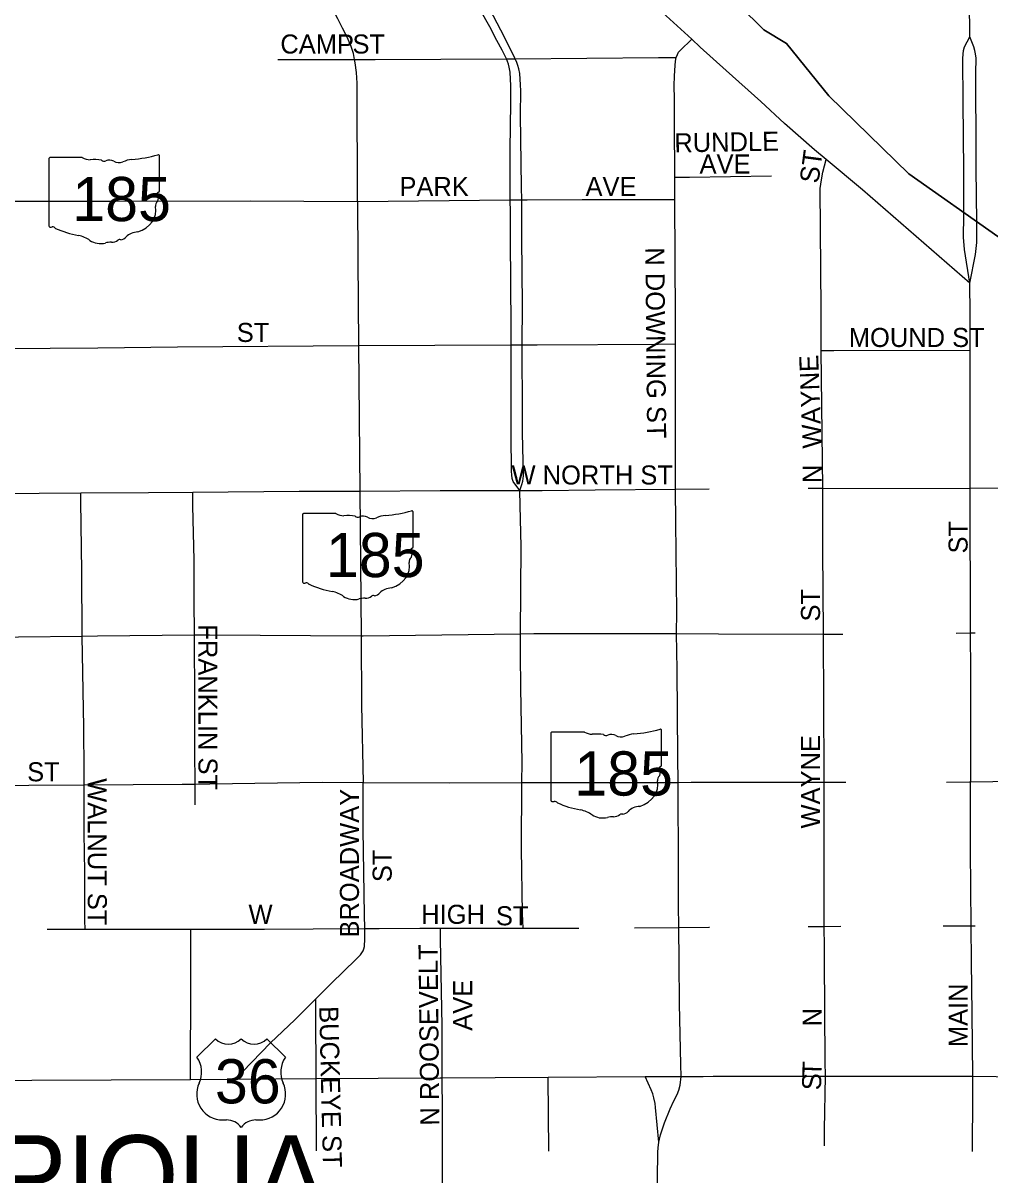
# Model space of a CAD drawing. Extents: x -87 to 2145, y -2128 to 440.
# Drawn here: x 533.8 to 609.9, y -568.8 to -478.1 of the extents above; entities that cross this region are included whole.
import ezdxf

# ---------------------------------------------------------------- set-up
doc = ezdxf.new("R2010")
doc.units = 0
for name, color, linetype in [('Default', 7, 'Continuous'), ('GM_X_City_Street', 7, 'Continuous'), ('GM_X_City_Street_Text', 7, 'Continuous'), ('GM_X_County_Road', 7, 'Continuous'), ('GM_X_State_Route', 7, 'Continuous'), ('GM_X_State_Shield', 7, 'Continuous'), ('GM_X_Township', 7, 'Continuous'), ('GM_X_US_Route', 7, 'Continuous'), ('GM_X_US_Shield', 7, 'Continuous')]:
    doc.layers.add(name, color=color, linetype=linetype)

msp = doc.modelspace()

# ---------------------------------------------------------------- linework, layer by layer
at = {"layer": 'Default'}
msp.add_circle((574.695, -533.387), 114.662, dxfattribs=at)
at = {"layer": 'GM_X_City_Street'}
for p, q in [((585.143, -514.819), (587.781, -514.8)), ((595.574, -514.742), (596.744, -514.734)), ((607.228, -526.149), (608.37, -526.135)), ((608.37, -526.135), (608.731, -526.137)), ((547.332, -539.66), (547.318, -538.032)), ((538.657, -549.463), (546.988, -549.456)), ((581.922, -549.35), (585.395, -549.325)), ((596.846, -549.232), (598.142, -549.227)), ((606.217, -549.189), (608.73, -549.192)), ((608.448, -552.036), (608.42, -549.191))]:
    msp.add_line(p, q, dxfattribs=at)
for points in [[(572.52, -480.945), (572.501, -480.904), (572.365, -480.612), (571.396, -478.679), (570.535, -477.026), (569.383, -474.98), (568.134, -472.73), (566.342, -469.116), (565.395, -467.299), (565.048, -466.741), (564.708, -466.247), (564.306, -465.722), (563.977, -465.454)], [(571.846, -480.948), (571.733, -480.732), (571.593, -480.466), (571.499, -480.266), (571.086, -479.505), (570.53, -478.438), (568.243, -474.397), (566.773, -471.457), (565.435, -468.813), (564.82, -467.586), (564.291, -466.513), (564.106, -466.077), (564.029, -465.816), (563.977, -465.454)], [(559.875, -480.99), (559.79, -480.517), (559.595, -479.981), (559.29, -479.248), (558.935, -478.528), (558.569, -477.808), (558.115, -476.944), (557.634, -476.01), (557.033, -474.846), (556.128, -473.097), (555.365, -471.622), (554.455, -469.86), (554.33, -469.617)], [(585.192, -480.833), (585.192, -480.83), (585.29, -480.592), (585.387, -480.43), (585.517, -480.3), (586.418, -479.398)], [(553.829, -480.995), (559.875, -480.99)], [(559.875, -480.99), (561.493, -480.988), (571.846, -480.948)], [(560.113, -492.173), (560.071, -482.874), (560.022, -482.019), (559.924, -481.262), (559.875, -480.99)], [(571.846, -480.948), (572.225, -480.946), (572.52, -480.945)], [(572.134, -492.049), (572.131, -491.45), (572.135, -488.089), (572.176, -484.445), (572.18, -483.067), (572.124, -481.99), (572.054, -481.606), (571.985, -481.377), (571.846, -480.948)], [(572.52, -480.945), (583.792, -480.845), (585.192, -480.833)], [(573.029, -492.04), (573.023, -491.049), (572.942, -485.344), (572.951, -483.464), (572.937, -483.001), (572.882, -482.113), (572.817, -481.72), (572.737, -481.48), (572.659, -481.245), (572.52, -480.945)], [(585.084, -490.272), (585.054, -485.976), (585.052, -484.102), (585.041, -483.072), (585.062, -482.292), (585.106, -481.48), (585.138, -481.123), (585.192, -480.833)], [(596.595, -503.899), (596.597, -500.678), (596.531, -491.161), (596.638, -490.48), (596.743, -489.863), (596.994, -488.876)], [(585.084, -490.272), (586.228, -490.254), (592.706, -490.151)], [(585.096, -492.015), (585.095, -491.921), (585.084, -490.272)], [(560.113, -492.173), (572.134, -492.049)], [(572.134, -492.049), (573.029, -492.04)], [(572.205, -503.459), (572.207, -502.046), (572.139, -495.171), (572.14, -493.004), (572.134, -492.049)], [(573.029, -492.04), (573.464, -492.035), (577.79, -492.018), (583.847, -492.016), (585.096, -492.015)], [(573.077, -503.455), (573.085, -500.342), (573.034, -495.052), (573.037, -493.438), (573.029, -492.04)], [(585.135, -503.392), (585.13, -501.319), (585.096, -492.015)], [(608.319, -498.615), (607.882, -495.963), (607.817, -494.979), (607.822, -494.687), (607.841, -493.576), (607.843, -493.46)], [(608.319, -498.615), (608.748, -496.357), (608.849, -495.412), (608.849, -495.346), (608.848, -494.198), (608.848, -494.19)], [(527.804, -503.767), (528.379, -503.762), (539.67, -503.692), (545.941, -503.608), (560.179, -503.512)], [(560.179, -503.512), (572.205, -503.459)], [(572.873, -514.922), (572.354, -514.222), (572.28, -513.971), (572.243, -513.704), (572.239, -513.439), (572.201, -510.58), (572.211, -508.125), (572.205, -503.736), (572.205, -503.459)], [(572.205, -503.459), (573.077, -503.455)], [(572.873, -514.922), (573.048, -514.443), (573.122, -514.178), (573.167, -513.778), (573.097, -510.397), (573.095, -507.916), (573.074, -504.447), (573.077, -503.455)], [(573.077, -503.455), (574.245, -503.45), (583.784, -503.399), (585.135, -503.392)], [(585.143, -514.819), (585.137, -513.766), (585.147, -507.878), (585.135, -503.392)], [(596.595, -503.899), (597.591, -503.897), (608.327, -503.87)], [(596.744, -514.734), (596.595, -503.899)], [(547.133, -515.046), (555.523, -514.986), (556.699, -514.986), (560.297, -514.967)], [(560.297, -514.967), (566.617, -514.933), (571.81, -514.925), (572.873, -514.922)], [(572.873, -514.922), (574.645, -514.917), (578.809, -514.866), (585.143, -514.819)], [(572.947, -526.204), (572.99, -519.339), (572.904, -516.098), (572.873, -514.922)], [(585.221, -526.186), (585.235, -524.499), (585.16, -517.405), (585.143, -514.819)], [(596.744, -514.734), (608.348, -514.775)], [(596.778, -526.238), (596.778, -526.119), (596.747, -519.584), (596.744, -514.734)], [(608.37, -526.135), (608.348, -514.775)], [(527.936, -515.185), (528.491, -515.184), (538.327, -515.11)], [(538.327, -515.11), (543.649, -515.07), (547.133, -515.046)], [(538.419, -526.38), (538.394, -521.276), (538.335, -515.789), (538.327, -515.11)], [(547.261, -526.296), (547.252, -523.544), (547.238, -520.402), (547.155, -516.132), (547.133, -515.046)], [(528.07, -526.478), (529.146, -526.472), (533.431, -526.438), (538.419, -526.38)], [(538.419, -526.38), (539.634, -526.367), (547.261, -526.296)], [(538.591, -538.101), (538.589, -537.074), (538.552, -533.544), (538.419, -526.38)], [(547.261, -526.296), (548.445, -526.285), (560.387, -526.354)], [(547.318, -538.032), (547.298, -535.408), (547.288, -531.583), (547.261, -526.296)], [(560.387, -526.354), (560.553, -526.355), (572.947, -526.204)], [(573.052, -537.918), (573.064, -536.33), (572.972, -530.485), (572.935, -527.799), (572.947, -526.204)], [(572.947, -526.204), (573.99, -526.192), (583.279, -526.181), (585.221, -526.186)], [(585.344, -537.897), (585.311, -535.885), (585.257, -529.003), (585.221, -526.186)], [(585.221, -526.186), (588.534, -526.195), (596.778, -526.238)], [(596.778, -526.238), (598.17, -526.245), (598.3, -526.243)], [(596.842, -537.877), (596.843, -537.146), (596.778, -526.238)], [(608.378, -537.859), (608.376, -529.16), (608.37, -526.135)], [(528.178, -538.196), (529.33, -538.19), (534.232, -538.119), (538.591, -538.101)], [(538.591, -538.101), (546.315, -538.039), (547.318, -538.032)], [(538.657, -549.463), (538.649, -548.77), (538.639, -544.931), (538.597, -541.886), (538.594, -539.265), (538.591, -538.101)], [(547.318, -538.032), (548.49, -538.025), (557.349, -537.892), (560.553, -537.917)], [(560.689, -549.403), (560.669, -548.317), (560.54, -541.632), (560.553, -537.917)], [(573.137, -549.372), (573.106, -548.227), (573.013, -543.123), (573.052, -537.918)], [(585.395, -549.325), (585.38, -547.55), (585.376, -544.134), (585.356, -538.628), (585.344, -537.897)], [(596.846, -549.232), (596.838, -548.315), (596.842, -537.877)], [(608.42, -549.191), (608.36, -543.197), (608.372, -537.859)], [(535.681, -549.467), (536.111, -549.466), (538.657, -549.463)], [(546.949, -561.279), (546.954, -560.174), (546.981, -554.605), (546.988, -549.457)], [(546.988, -549.457), (552.777, -549.451), (556.603, -549.427), (560.689, -549.403)], [(556.819, -554.94), (558.023, -553.731), (560.011, -551.829), (560.336, -551.473), (560.447, -551.311), (560.544, -551.172), (560.602, -550.994), (560.658, -550.818), (560.669, -550.622), (560.678, -550.425), (560.678, -549.843), (560.689, -549.403)], [(560.689, -549.403), (561.8, -549.396), (565.022, -549.375), (566.627, -549.375)], [(566.627, -549.375), (573.137, -549.372)], [(566.766, -561.159), (566.76, -560.475), (566.762, -557.056), (566.643, -550.279), (566.627, -549.375)], [(573.137, -549.372), (574.539, -549.372), (576.997, -549.372), (577.539, -549.371)], [(585.395, -549.325), (587.76, -549.309), (587.819, -549.308)], [(585.583, -561.047), (585.56, -560.098), (585.448, -555.32), (585.419, -551.976), (585.395, -549.325)], [(595.581, -549.243), (595.697, -549.242), (596.846, -549.232)], [(596.867, -551.807), (596.86, -550.867), (596.846, -549.232)], [(596.935, -561.03), (596.927, -559.874), (596.867, -551.807)], [(608.536, -561.022), (608.488, -556.076), (608.448, -552.036)], [(550.499, -561.257), (551.046, -560.69), (553.246, -558.407), (555.177, -556.59), (556.819, -554.94)], [(556.848, -561.219), (556.823, -555.838), (556.819, -554.94)], [(556.874, -566.907), (556.848, -561.219)], [(566.837, -571.437), (566.833, -571.116), (566.794, -568.091), (566.789, -563.755), (566.766, -561.159)], [(575.174, -566.923), (575.122, -561.094)], [(583.83, -566.221), (583.56, -563.488), (583.528, -563.167), (583.442, -562.737), (583.342, -562.408), (583.228, -562.093), (582.755, -561.059)], [(583.83, -566.221), (583.947, -565.645), (584.264, -564.703), (584.71, -563.605), (584.997, -562.98), (585.267, -562.463), (585.407, -562.115), (585.5, -561.742), (585.583, -561.047)], [(596.877, -566.514), (596.857, -565.231), (596.935, -561.03)], [(608.514, -566.956), (608.549, -562.458), (608.536, -561.022)], [(583.698, -571.33), (583.701, -571.103), (583.75, -567.029), (583.771, -566.637), (583.823, -566.253), (583.83, -566.221)]]:
    msp.add_lwpolyline(points, dxfattribs=at)
at = {"layer": 'GM_X_County_Road'}
for points in [[(608.302, -479.226), (608.302, -479.226), (608.223, -470.582), (608.19, -465.498), (608.19, -462.628), (608.323, -460.023)], [(607.843, -493.46), (607.831, -490.459), (607.828, -489.729), (607.78, -484.336), (607.757, -480.91), (607.773, -480.589), (607.821, -480.301), (607.902, -479.996), (608.302, -479.226)], [(608.811, -490.005), (608.796, -488.442), (608.792, -482.065), (608.799, -480.894), (608.768, -480.558), (608.704, -480.285), (608.623, -480.012), (608.302, -479.226)], [(608.848, -494.19), (608.822, -491.283), (608.811, -490.005)]]:
    msp.add_lwpolyline(points, dxfattribs=at)
at = {"layer": 'GM_X_State_Route'}
msp.add_line((606.476, -537.886), (619.951, -537.692), dxfattribs=at)
for points in [[(608.323, -501.003), (608.319, -498.615), (599.866, -491.261), (596.994, -488.876), (596.084, -488.119), (593.721, -486.042), (591.846, -484.3), (589.139, -481.861), (587.09, -480.016), (586.418, -479.398), (584.121, -477.286), (584.085, -477.251)], [(476.344, -492.457), (485.078, -492.404), (491.685, -492.386), (504.576, -492.351), (516.628, -492.319), (517.71, -492.317), (527.667, -492.199), (532.465, -492.143), (533.359, -492.145), (540.704, -492.157), (551.648, -492.114), (560.113, -492.173)], [(560.113, -492.173), (560.136, -496.707), (560.179, -503.512), (560.297, -514.967), (560.387, -526.354), (560.43, -531.833), (560.553, -537.917)], [(611.816, -514.742), (608.348, -514.775), (608.332, -507.006), (608.327, -503.87), (608.323, -501.003)], [(560.553, -537.917), (567.319, -537.93), (573.052, -537.918), (576.745, -537.909), (585.344, -537.897), (586.365, -537.896), (596.842, -537.877), (598.551, -537.875)]]:
    msp.add_lwpolyline(points, dxfattribs=at)
at = {"layer": 'GM_X_State_Shield'}
for p, q in [((538.442, -488.722), (535.894, -488.722)), ((544.509, -491.354), (544.509, -488.591)), ((535.808, -488.812), (535.808, -494.096)), ((544.508, -491.354), (544.509, -491.354)), ((555.777, -516.834), (555.777, -522.117)), ((558.411, -516.743), (555.863, -516.743)), ((564.478, -519.375), (564.478, -516.612)), ((564.478, -519.375), (564.478, -519.375)), ((575.329, -534.028), (575.329, -539.311)), ((577.963, -533.937), (575.415, -533.937)), ((584.03, -536.57), (584.03, -533.806)), ((584.029, -536.569), (584.03, -536.57))]:
    msp.add_line(p, q, dxfattribs=at)
for centre, major_axis, start_param, end_param in [((535.908, -488.801), (0.101, 0), 1.712693, 3.28349), ((539.049, -488.108), (0.978, 0), 4.042523, 4.731795), ((541.41, -481.519), (9.227, 0), 4.814394, 5.042369), ((544.413, -488.579), (0.0969, 0), 6.141152, 7.989035), ((539.373, -491.688), (3.51, 0), 1.404758, 1.657858), ((540.17, -488.774), (0.282, 0), 3.836095, 5.185415), ((540.584, -489.384), (0.586, 0), 0.950623, 2.079405), ((541.341, -488.547), (0.705, 0), 4.081561, 5.145723), ((542.587, -490.335), (1.856, 0), 1.699011, 2.107814), ((544.487, -491.557), (0.15, 0), 1.883978, 3.671073), ((544.406, -491.365), (0.104, 0), 5.05454, 6.418171), ((544.856, -492.511), (0.655, 0), 2.387724, 3.262537), ((543.533, -491.907), (0.9, 0), 5.934695, 6.695948), ((541.927, -492.862), (2.308, 0), 5.101752, 6.440018), ((535.909, -494.107), (0.102, 0), 3.00124, 4.508301), ((536.083, -494.4), (0.28, 0), 0.519207, 1.627899), ((535.924, -493.567), (0.776, 0), 4.665946, 4.897461), ((539.616, -489.654), (6.663, 0), 4.195997, 4.488961), ((537.629, -496.469), (2.085, 0), 0.823519, 1.323587), ((541.298, -494.608), (0.746, 0), 4.937069, 5.64225), ((542.9, -495.579), (1.264, 0), 1.647645, 2.488434), ((539.884, -494.427), (1.323, 0), 4.026481, 4.996735), ((540.649, -496.253), (1.087, 0), 1.495662, 1.94098), ((540.745, -494.822), (0.705, 0), 4.691044, 5.507374), ((541.383, -495.334), (0.198, 0), 1.147584, 2.315152), ((555.877, -516.822), (0.101, 0), 1.712693, 3.28349), ((559.018, -516.129), (0.978, 0), 4.042523, 4.731795), ((561.379, -509.54), (9.227, 0), 4.814394, 5.042369), ((564.382, -516.6), (0.0969, 0), 6.141152, 7.989035), ((559.342, -519.709), (3.51, 0), 1.404758, 1.657858), ((560.139, -516.795), (0.282, 0), 3.836095, 5.185415), ((560.553, -517.406), (0.586, 0), 0.950623, 2.079405), ((561.31, -516.568), (0.705, 0), 4.081561, 5.145723), ((562.556, -518.356), (1.856, 0), 1.699011, 2.107814), ((564.456, -519.578), (0.15, 0), 1.883978, 3.671073), ((564.375, -519.386), (0.104, 0), 5.05454, 6.418171), ((564.825, -520.532), (0.655, 0), 2.387724, 3.262537), ((563.502, -519.928), (0.9, 0), 5.934695, 6.695948), ((561.896, -520.884), (2.308, 0), 5.101752, 6.440018), ((555.878, -522.128), (0.102, 0), 3.00124, 4.508301), ((555.893, -521.588), (0.776, 0), 4.665946, 4.897461), ((556.052, -522.422), (0.28, 0), 0.519207, 1.627899), ((559.585, -517.675), (6.663, 0), 4.195997, 4.488961), ((557.599, -524.49), (2.085, 0), 0.823519, 1.323587), ((561.352, -523.355), (0.198, 0), 1.147584, 2.315152), ((561.268, -522.629), (0.746, 0), 4.937069, 5.64225), ((562.869, -523.6), (1.264, 0), 1.647645, 2.488434), ((559.853, -522.448), (1.323, 0), 4.026481, 4.996735), ((560.618, -524.274), (1.087, 0), 1.495662, 1.94098), ((560.714, -522.843), (0.705, 0), 4.691044, 5.507374), ((575.429, -534.017), (0.101, 0), 1.712693, 3.28349), ((578.57, -533.324), (0.978, 0), 4.042523, 4.731795), ((580.93, -526.735), (9.227, 0), 4.814394, 5.042369), ((583.933, -533.795), (0.0969, 0), 6.141152, 7.989035), ((578.894, -536.903), (3.51, 0), 1.404758, 1.657858), ((579.691, -533.99), (0.282, 0), 3.836095, 5.185415), ((580.105, -534.6), (0.586, 0), 0.950623, 2.079405), ((580.862, -533.763), (0.705, 0), 4.081561, 5.145723), ((582.107, -535.551), (1.856, 0), 1.699011, 2.107814), ((584.008, -536.773), (0.15, 0), 1.883978, 3.671073), ((583.927, -536.581), (0.104, 0), 5.05454, 6.418171), ((584.377, -537.727), (0.655, 0), 2.387724, 3.262537), ((583.054, -537.122), (0.9, 0), 5.934695, 6.695948), ((581.447, -538.078), (2.308, 0), 5.101752, 6.440018), ((575.429, -539.323), (0.102, 0), 3.00124, 4.508301), ((575.445, -538.782), (0.776, 0), 4.665946, 4.897461), ((575.604, -539.616), (0.28, 0), 0.519207, 1.627899), ((579.137, -534.869), (6.663, 0), 4.195997, 4.488961), ((577.15, -541.685), (2.085, 0), 0.823519, 1.323587), ((580.904, -540.55), (0.198, 0), 1.147584, 2.315152), ((580.819, -539.823), (0.746, 0), 4.937069, 5.64225), ((582.421, -540.795), (1.264, 0), 1.647645, 2.488434), ((579.405, -539.642), (1.323, 0), 4.026481, 4.996735), ((580.169, -541.469), (1.087, 0), 1.495662, 1.94098), ((580.266, -540.038), (0.705, 0), 4.691044, 5.507374)]:
    msp.add_ellipse(centre, major_axis=major_axis, ratio=0.8, start_param=start_param, end_param=end_param, dxfattribs=at)
at = {"layer": 'GM_X_Township'}
for points in [[(566.271, -419.035), (566.574, -419.96), (567.487, -424.351), (567.831, -431.137), (567.688, -438.398), (567.842, -440.741), (569.351, -450.963), (571.927, -457.295), (574.054, -460.801), (575.481, -462.437), (577.21, -463.897), (580.715, -467.959), (586.316, -472.943), (592.09, -478.65), (593.884, -479.749), (597.208, -483.869), (603.519, -490.001), (610.505, -494.939), (618.775, -498.147), (620.391, -499.004), (626.263, -500.646)], [(626.263, -500.646), (620.391, -499.004), (618.775, -498.147), (610.505, -494.939), (603.519, -490.001), (597.208, -483.869), (593.884, -479.749), (592.09, -478.65), (586.316, -472.943), (580.715, -467.959), (577.21, -463.897), (575.481, -462.437), (574.054, -460.801), (571.927, -457.295), (569.351, -450.963), (567.842, -440.741), (567.688, -438.398), (567.831, -431.137), (567.487, -424.351), (566.574, -419.96), (566.271, -419.035)]]:
    msp.add_lwpolyline(points, dxfattribs=at)
at = {"layer": 'GM_X_US_Route'}
for points in [[(528.188, -561.373), (546.949, -561.279), (550.499, -561.257), (556.848, -561.219), (566.614, -561.16), (566.766, -561.159), (575.122, -561.094), (582.755, -561.059), (585.583, -561.047), (587.317, -561.039)], [(587.317, -561.039), (588.095, -561.036), (596.935, -561.03)], [(596.935, -561.03), (607.65, -561.023), (608.536, -561.022)], [(608.536, -561.022), (615.879, -561.138), (620.053, -561.132), (620.048, -560.496)]]:
    msp.add_lwpolyline(points, dxfattribs=at)
at = {"layer": 'GM_X_US_Shield'}
for p, q in [((548.919, -558.093), (547.469, -559.543)), ((554.43, -559.543), (552.98, -558.093)), ((549.499, -564.473), (549.789, -564.473)), ((552.11, -564.473), (552.4, -564.473))]:
    msp.add_line(p, q, dxfattribs=at)
for centre, radius, start, end in [((549.934, -557.057), 1.45, 225.573, 314.427), ((551.965, -557.057), 1.45, 225.573, 314.427), ((545.806, -560.707), 2.03, 334.54712, 35.00093), ((556.093, -560.707), 2.03, 144.99907, 205.45288), ((549.477, -562.443), 2.03, 154.83192, 270.63826), ((552.422, -562.443), 2.03, 269.36174, 25.16808), ((549.789, -565.924), 1.45, 36.8699, 90), ((552.11, -565.924), 1.45, 90, 143.1301)]:
    msp.add_arc(centre, radius, start, end, dxfattribs=at)

# ---------------------------------------------------------------- texts
at = {"layer": 'Default'}
msp.add_text('CITY OF PIQUA', height=6.255, rotation=0.00001, dxfattribs=at).set_placement((496.298, -571.93))
at = {"layer": 'GM_X_City_Street_Text'}
for s, rotation, p in [('CAMP', 0.00001, (554.033, -480.528)), ('ST', 0.00001, (559.709, -480.528)), ('RUNDLE', 1.00536, (585.06, -488.316)), ('AVE', 0.00001, (587.033, -489.973)), ('ST', 82.39383, (596.39, -490.799)), ('PARK', 0.00001, (563.405, -491.748)), ('AVE', 0.00001, (578.057, -491.748)), ('N DOWNING ST', 270.57299, (582.759, -495.792)), ('ST', 0.00001, (550.601, -503.232)), ('MOUND ST', 0.00001, (598.781, -503.628)), ('WAYNE', 92.20567, (596.651, -511.577)), ('W NORTH ST', 0.00001, (572.231, -514.452)), ('N', 90, (596.651, -514.338)), ('ST', 90, (608.135, -519.882)), ('ST', 90, (596.518, -525.237)), ('FRANKLIN ST', 270, (547.583, -525.461)), ('WAYNE', 90, (596.518, -541.53)), ('ST', 0.00001, (534.101, -537.816)), ('WALNUT ST', 270, (538.872, -537.57)), ('BROADWAY', 90, (560.219, -550.11)), ('ST', 90, (562.799, -545.754)), ('W', 0.00001, (551.525, -549.037)), ('HIGH', 0.00001, (565.121, -549.036)), ('ST', 0.00001, (571.002, -549.151)), ('N ROOSEVELT', 90.60875, (566.555, -564.91)), ('AVE', 90, (569.136, -557.45)), ('MAIN', 90, (608.135, -558.741)), ('BUCKEYE ST', 271.36524, (557.088, -555.531)), ('N', 90, (596.651, -557.106)), ('T', 88.63811, (596.619, -561.091)), ('S', 88.6068, (596.593, -562.147))]:
    msp.add_text(s, height=1.5, rotation=rotation, dxfattribs=at).set_placement(p)
at = {"layer": 'GM_X_State_Shield'}
for p in [(537.653, -493.723), (557.622, -521.744), (577.174, -538.939)]:
    msp.add_text('185', height=3.4805, dxfattribs=at).set_placement(p)
at = {"layer": 'GM_X_US_Shield'}
msp.add_text('36', height=3.4805, dxfattribs=at).set_placement((548.881, -563.168))

doc.saveas('drawing.dxf')
